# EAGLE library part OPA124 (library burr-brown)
Difet Operational Amplifier Low Noise, Precision
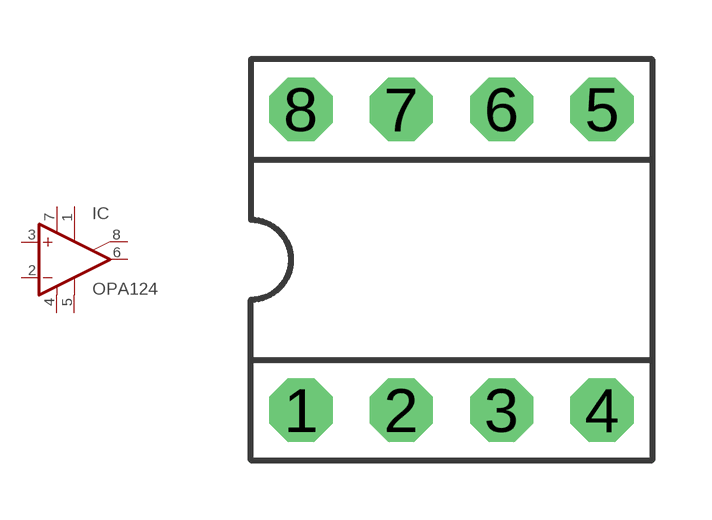
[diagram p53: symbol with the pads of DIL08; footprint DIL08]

Designator prefix IC

## OPA124P (OC_FARNELL: unknown; OC_NEWARK: unknown)  [DIL08]
1  TRIM1  pas
2  -IN  in
3  +IN  in
4  V-  pwr
5  TRIM2  pas
6  OUT  out
7  V+  pwr
8  SUBS  pas

## Footprint DIL08 (pad centres in mm)
Dual In Line
drill 0.813 pad 1.6 octagon: 1 -3.81,-3.81; 2 -1.27,-3.81; 3 1.27,-3.81; 4 3.81,-3.81; 5 3.81,3.81; 6 1.27,3.81; 7 -1.27,3.81; 8 -3.81,3.81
